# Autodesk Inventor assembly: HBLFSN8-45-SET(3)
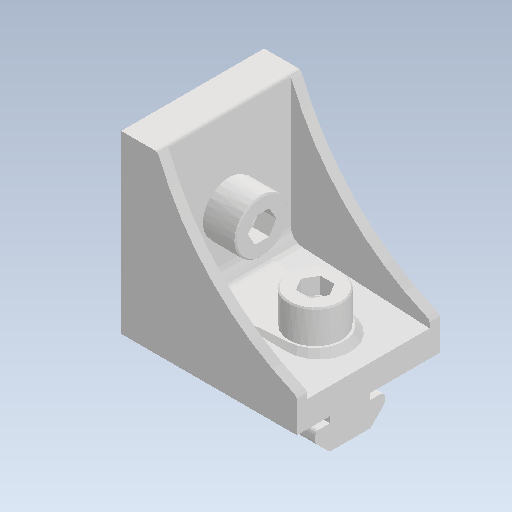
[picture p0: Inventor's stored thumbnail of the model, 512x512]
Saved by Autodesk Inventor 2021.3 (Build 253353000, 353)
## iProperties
Created: 2022-02
Part Number: HBLFSN8-45-SET(3)
Document SubType Name: Assembly
Designer: kengo
Author: kengo
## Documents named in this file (4)
- C:\Users\kengo\Documents\S2S_frame\SDC345\frame_misumi_ver12\HBLFSN8-45-SET(3).iam
- C:\Users\kengo\Documents\S2S_frame\SDC345\frame_misumi_ver12\HBLFSN8-45.ipt
- C:\Users\kengo\Documents\S2S_frame\SDC345\frame_misumi_ver12\HNTT8-8.ipt
- C:\Users\kengo\Documents\S2S_frame\SDC345\frame_misumi_ver12\CBM8-20.ipt
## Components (5 placed, 3 different names)
1. HBLFSN8-45
2. HNTT8-8
3. CBM8-20
4. HNTT8-8:1
5. CBM8-20:1
